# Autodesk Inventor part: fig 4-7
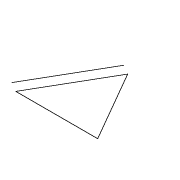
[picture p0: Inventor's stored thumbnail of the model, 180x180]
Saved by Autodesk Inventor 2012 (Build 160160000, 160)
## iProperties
Created: 2005-02
Part Number: fig 4-7
Document SubType Name: Modeling
Designer: CADCIM
Manufacturer: Standard
Standards Organization: Custom
Density: 1 g/cm^3
Material: Default
Author: CADCIM
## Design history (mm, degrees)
sketch "Sketch1"
  geometry: L1 (-3.883, 28.419)-(-24.946, -8.063); L2 (-24.946, -8.063)-(17.18, -8.063); L3 (17.18, -8.063)-(-3.883, 28.419); L4 (-8.847, 31.285)-(-29.909, -5.197)
  constraints: 8 end point, 2 equal length, 1 horizontal, 1 parallel, 1 other
